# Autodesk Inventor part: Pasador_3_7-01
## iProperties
Created: 2008-01
Part Number: Pasador_3_7-01
Document SubType Name: Modeling
Designer: eruiz-tagle
Density: 1 g/cm^3
Mass: 0.351876 g
Surface Area: 4.46973 cm^2
Volume: 0.351876 cm^3
Author: eruiz-tagle
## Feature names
1. Extrusion1
2. Fillet1
